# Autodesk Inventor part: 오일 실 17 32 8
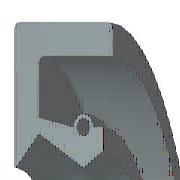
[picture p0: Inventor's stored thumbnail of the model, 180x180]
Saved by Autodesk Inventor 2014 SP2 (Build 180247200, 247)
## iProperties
IsCustomPart: 0
Created: 2018-09
Part Number: 오일 실 17 32 8
Material: 고무
Description: 오일-실
Document SubType Name: Modeling
Standard: KS B 2804
Standards Organization: KS
Language: ko-KR
Size Designation: D - 17 32 8
Categories: <MemberInstance><Categories><Category DisplayName="샤프트 부품" InternalName="7f7aeb1f-a693-4053-b835-cee3144e0d98" Mnemonic="SHFT"><Category DisplayName="실링" Intern
Density: 0.93 g/cm^3
Appearance: 고무 - 검은색 - 버전 1.1
Mass: 2.28027 g
Surface Area: 32.1224 cm^2
Volume: 2.45191 cm^3
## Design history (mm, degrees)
revolve "본체" stored, may be unused: angle "d17" = 90 deg
revolve "스프링1" stored, may be unused: angle "d18" = 90 deg
body "Solid1"
sketch "스케치1"
  geometry: L1 (0, 16)-(8, 16); L2 (8, 14.25)-(1.75, 14.25); L3 (1.75, 10.25)-(4.9, 8.5); L4 (4.9, 8.5)-(0, 8.5); L5 (0, 0)-(9.586, 0) reference; L6 (4.9, 8.5)-(6.3, 9.375); L7 (0, 18)-(0, -3) reference; L8 (-1.941, 0)-(11.507, 0) reference; L9 (4.2, 10.6)-(1.75, 11.21); L10 (1.75, 11.21)-(1.75, 14.25); L11 (0, 16)-(0, 8.588); L12 (4.9, 8.5)-(0, 8.5); L13 (1.75, 10.25)-(0.152, 8.528); L14 (8, 16)-(8, 14.25); L15 (5.6, 10.6)-(6.3, 10.6); L16 (6.3, 10.6)-(6.3, 9.375); C1 r 0.455 at (4.9, 10.6); A1 r 0.7 centre (4.9, 10.6) between (5.6, 10.6) and (4.2, 10.6); A2 r 0.088 centre (0.088, 8.588) between (0, 8.588) and (0.152, 8.528); 1 further point
  constraints: 28 end point, 5 horizontal alignment, 5 point on line, 4 point on circle, 4 vertical alignment, 3 centre point, 3 tangent, 2 collinear, 2 horizontal, 2 perpendicular, 1 coincident, 1 parallel
  dimensions: "d0" = 32 diameter of L1 L5 (= SD2); "d1" = 1.75 distance of L1.end L2.start (= SD); "d2" = 0.91 diameter of C1 (= SPDI); "d3" = 1.4 diameter of A1 (= SPDA); "d4" = 17 diameter of L3.end L5 (= NND); "d5" = 20.5 diameter of L3.start L5 (= TKDM); "d7" = 22.42 diameter of L9.end L5 (= TKDM + 0.24 x SWDT); "d8" = 1.75 distance between parallel lines of L11 L10 (= SD); "d9" = 4.9 distance from line of L11 C1.centre (= SPDST); "d10" = 21.2 diameter of C1.centre L5 (= HLDM); "d11" = 0.0875 radius of A2 (= 0.25 x LAB); "d12" = 6.3 distance between parallel lines of L11 L16 (= SDI); "d13" = 18.75 diameter of L6.end L5 (= ABDM); "d14" = 8 distance from line of L11 L1.end (= SWDT)
fillet "모깎기1" dims "d6" = 0.3 (= RR)
other parameters: "SD2" = 32 [user parameter; used in 1 equation term], "SWDT" = 8 [user parameter; used in 2 equation terms], "RR" = 0.3 [user parameter; used in 1 equation term], "SD" = 1.75 [user parameter; used in 2 equation terms], "NND" = 17 [user parameter; used in 1 equation term], "SPDA" = 1.4 [user parameter; used in 1 equation term], "SPDI" = 0.91 [user parameter; used in 1 equation term], "TKDM" = 20.5 [user parameter; used in 2 equation terms], "HLDM" = 21.2 [user parameter; used in 1 equation term], "ABDM" = 18.75 [user parameter; used in 1 equation term], "SDI" = 6.3 [user parameter; used in 1 equation term], "SPDST" = 4.9 [user parameter; used in 1 equation term], "LAB" = 0.35 [user parameter; used in 1 equation term], "d15" = 0, "d16" = 0, "d19" = 0
